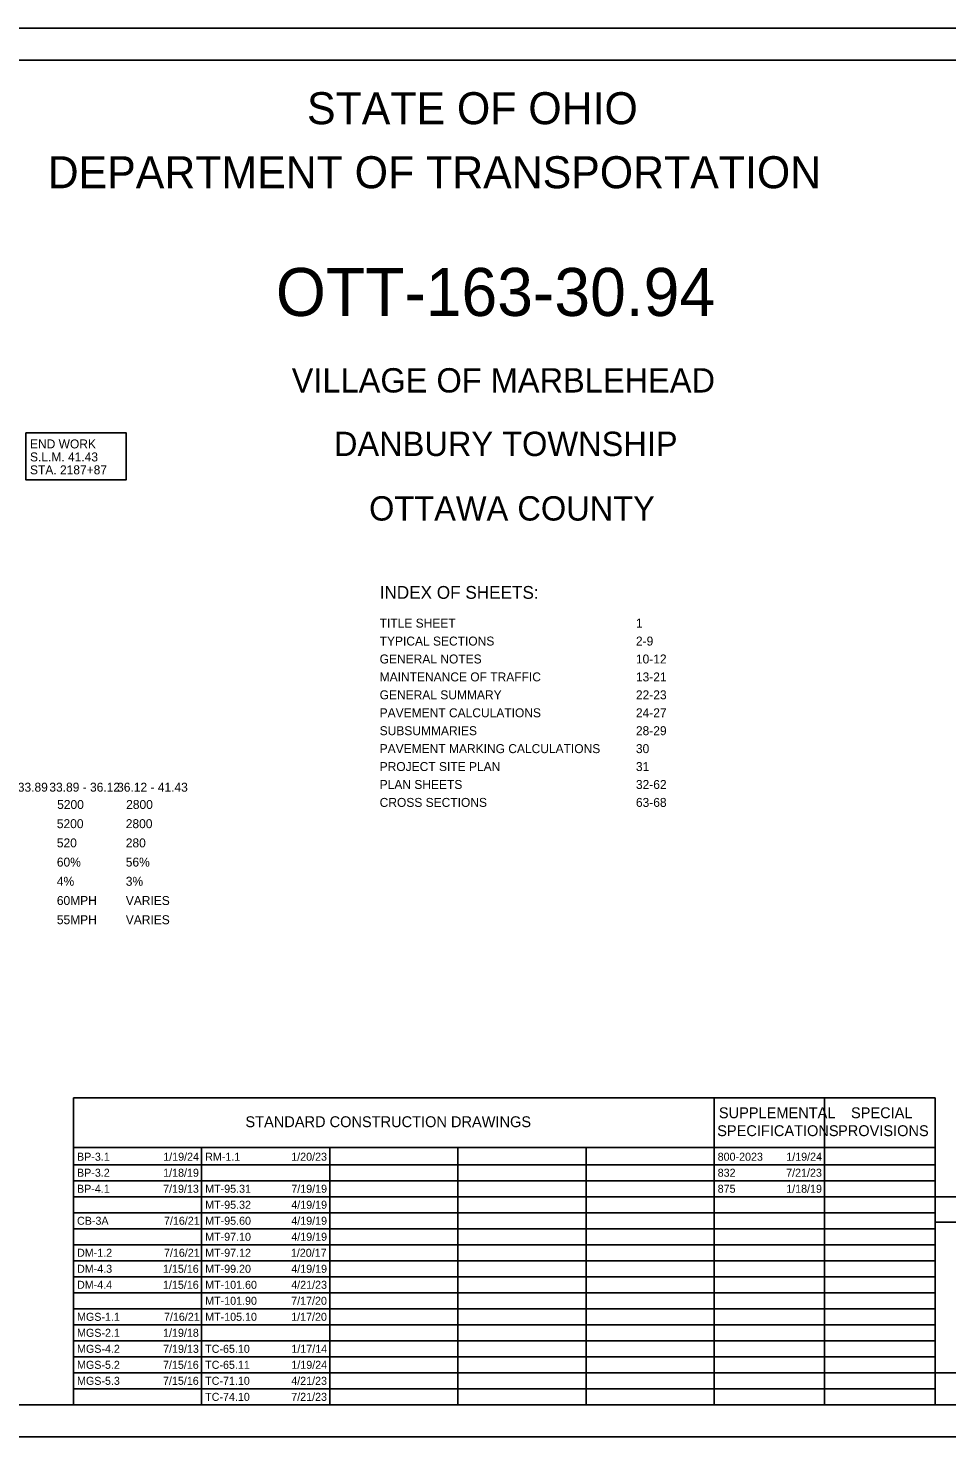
# Model space of a CAD drawing. Extents: x -12 to 34, y 0 to 22.
# Drawn here: x 9.44 to 23.78, y 0 to 22 of the extents above; entities that cross this region are included whole.
import ezdxf

# ---------------------------------------------------------------- set-up
doc = ezdxf.new("R2010")
doc.units = 0
for name, color, linetype in [('GM_X_Adjacent_County', 7, 'Continuous'), ('GM_X_County', 7, 'Continuous'), ('GM_X_Section', 7, 'Continuous'), ('GM_X_Township', 7, 'Continuous')]:
    doc.layers.add(name, color=color, linetype=linetype)

msp = doc.modelspace()

# ---------------------------------------------------------------- linework, layer by layer
at = {"layer": 'GM_X_Adjacent_County'}
msp.add_lwpolyline([(9.406, 15.682), (10.972, 15.682), (10.972, 14.944), (9.406, 14.944)], close=True, dxfattribs=at)
at = {"layer": 'GM_X_County'}
msp.add_lwpolyline([(1.5, 21.5), (33.5, 21.5), (33.5, 0.5), (1.5, 0.5)], close=True, dxfattribs=at)
at = {"layer": 'GM_X_Section'}
msp.add_lwpolyline([(0, 0), (34, 0), (34, 22), (0, 22)], close=True, dxfattribs=at)
at = {"layer": 'GM_X_Township'}
for p, q in [((10.15, 5.292), (23.6, 5.292)), ((10.15, 0.5), (10.15, 5.292)), ((20.15, 0.5), (20.15, 5.292)), ((21.875, 0.5), (21.875, 5.292)), ((23.6, 0.5), (23.6, 5.292)), ((10.15, 4.521), (23.6, 4.521)), ((12.15, 0.5), (12.15, 4.521)), ((14.15, 0.5), (14.15, 4.521)), ((16.15, 0.5), (16.15, 4.521)), ((18.15, 0.5), (18.15, 4.521)), ((10.15, 4.25), (23.6, 4.25)), ((10.15, 4), (23.6, 4)), ((10.15, 3.75), (23.6, 3.75)), ((23.6, 0.5), (23.6, 3.75)), ((23.6, 3.75), (26.4, 3.75)), ((10.15, 3.5), (23.6, 3.5)), ((23.6, 3.35), (26.4, 3.35)), ((10.15, 3.25), (23.6, 3.25)), ((10.15, 3), (23.6, 3)), ((10.15, 2.75), (23.6, 2.75)), ((10.15, 2.5), (23.6, 2.5)), ((10.15, 2.25), (23.6, 2.25)), ((10.15, 2), (23.6, 2)), ((10.15, 1.75), (23.6, 1.75)), ((10.15, 1.5), (23.6, 1.5)), ((10.15, 1.25), (23.6, 1.25)), ((10.15, 1), (23.6, 1)), ((10.15, 0.75), (23.6, 0.75)), ((23.6, 0.5), (26.4, 0.5))]:
    msp.add_line(p, q, dxfattribs=at)
msp.add_lwpolyline([(23.6, 0.5), (23.6, 1), (26.4, 1), (26.4, 0.5)], close=True, dxfattribs=at)

# ---------------------------------------------------------------- texts
at = {"layer": 'GM_X_Adjacent_County'}
for s, height, p in [('STATE OF OHIO', 0.5, (13.795, 20.5)), ('DEPARTMENT OF TRANSPORTATION', 0.5, (9.747, 19.5)), ('OTT-163-30.94', 0.75, (13.309, 17.505)), ('VILLAGE OF MARBLEHEAD', 0.38, (13.556, 16.31)), ('  DANBURY TOWNSHIP  ', 0.38, (13.933, 15.318)), ('END WORK', 0.14, (9.471, 15.437)), ('S.L.M. 41.43', 0.14, (9.471, 15.234)), ('STA. 2187+87', 0.14, (9.471, 15.032)), ('    OTTAWA COUNTY   ', 0.38, (14.199, 14.31)), ('INDEX OF SHEETS:', 0.2, (14.929, 13.088)), ('TITLE SHEET                        ', 0.14, (14.929, 12.638)), ('1      ', 0.14, (18.929, 12.638)), ('TYPICAL SECTIONS                   ', 0.14, (14.929, 12.358)), ('2-9    ', 0.14, (18.929, 12.358)), ('GENERAL NOTES                      ', 0.14, (14.929, 12.078)), ('10-12  ', 0.14, (18.929, 12.078)), ('MAINTENANCE OF TRAFFIC             ', 0.14, (14.929, 11.798)), ('13-21  ', 0.14, (18.929, 11.798)), ('GENERAL SUMMARY                    ', 0.14, (14.929, 11.518)), ('22-23  ', 0.14, (18.929, 11.518)), ('PAVEMENT CALCULATIONS              ', 0.14, (14.929, 11.238)), ('24-27  ', 0.14, (18.929, 11.238)), ('SUBSUMMARIES                       ', 0.14, (14.929, 10.958)), ('28-29  ', 0.14, (18.929, 10.958)), ('PAVEMENT MARKING CALCULATIONS      ', 0.14, (14.929, 10.678)), ('30     ', 0.14, (18.929, 10.678)), ('PROJECT SITE PLAN                  ', 0.14, (14.929, 10.398)), ('31     ', 0.14, (18.929, 10.398)), ('PLAN SHEETS                        ', 0.14, (14.929, 10.118)), ('32-62  ', 0.14, (18.929, 10.118)), ('5200  ', 0.14, (9.895, 9.806)), ('2800  ', 0.14, (10.972, 9.806)), ('CROSS SECTIONS                     ', 0.14, (14.929, 9.838)), ('63-68  ', 0.14, (18.929, 9.838)), ('5200  ', 0.14, (9.89, 9.506)), ('2800  ', 0.14, (10.966, 9.506)), ('520   ', 0.14, (9.89, 9.206)), ('280   ', 0.14, (10.966, 9.206)), ('60%   ', 0.14, (9.89, 8.906)), ('56%   ', 0.14, (10.966, 8.906)), ('4%    ', 0.14, (9.89, 8.606)), ('3%    ', 0.14, (10.966, 8.606)), ('60MPH ', 0.14, (9.89, 8.306)), ('VARIES', 0.14, (10.966, 8.306)), ('55MPH ', 0.14, (9.89, 8.006)), ('VARIES', 0.14, (10.966, 8.006)), ('SUPPLEMENTAL', 0.17, (20.224, 4.976)), ('SPECIAL', 0.17, (22.286, 4.976)), ('STANDARD CONSTRUCTION DRAWINGS', 0.17, (12.834, 4.836)), ('SPECIFICATIONS', 0.17, (20.198, 4.696)), ('PROVISIONS', 0.17, (22.084, 4.696))]:
    msp.add_text(s, height=height, dxfattribs=at).set_placement(p)
at = {"layer": 'GM_X_Township'}
for s, height, p in [('31.77 - 33.89', 0.14, (8.646, 10.076)), ('33.89 - 36.12', 0.14, (9.773, 10.076)), ('36.12 - 41.43', 0.14, (10.831, 10.076)), ('BP-3.1', 0.125, (10.205, 4.312)), ('1/19/24', 0.125, (11.551, 4.312)), ('RM-1.1', 0.125, (12.205, 4.312)), ('1/20/23', 0.125, (13.549, 4.312)), ('800-2023', 0.125, (20.205, 4.312)), ('1/19/24', 0.125, (21.276, 4.312)), ('BP-3.2', 0.125, (10.205, 4.062)), ('1/18/19', 0.125, (11.55, 4.062)), ('832', 0.125, (20.205, 4.062)), ('7/21/23', 0.125, (21.274, 4.062)), ('-', 0.125, (21.768, 4.312)), ('BP-4.1', 0.125, (10.205, 3.812)), ('7/19/13', 0.125, (11.549, 3.812)), ('MT-95.31', 0.125, (12.205, 3.812)), ('7/19/19', 0.125, (13.55, 3.812)), ('875', 0.125, (20.205, 3.812)), ('1/18/19', 0.125, (21.275, 3.812)), ('MT-95.32', 0.125, (12.205, 3.562)), ('4/19/19', 0.125, (13.55, 3.562)), ('CB-3A', 0.125, (10.205, 3.312)), ('7/16/21', 0.125, (11.562, 3.312)), ('MT-95.60', 0.125, (12.205, 3.312)), ('4/19/19', 0.125, (13.55, 3.312)), ('MT-97.10', 0.125, (12.205, 3.062)), ('4/19/19', 0.125, (13.55, 3.062)), ('DM-1.2', 0.125, (10.205, 2.812)), ('7/16/21', 0.125, (11.562, 2.812)), ('MT-97.12', 0.125, (12.205, 2.812)), ('1/20/17', 0.125, (13.543, 2.812)), ('DM-4.3', 0.125, (10.205, 2.562)), ('1/15/16', 0.125, (11.547, 2.562)), ('MT-99.20', 0.125, (12.205, 2.562)), ('4/19/19', 0.125, (13.55, 2.562)), ('DM-4.4', 0.125, (10.205, 2.312)), ('1/15/16', 0.125, (11.547, 2.312)), ('MT-101.60', 0.125, (12.205, 2.312)), ('4/21/23', 0.125, (13.549, 2.312)), ('MT-101.90', 0.125, (12.205, 2.062)), ('7/17/20', 0.125, (13.548, 2.062)), ('MGS-1.1', 0.125, (10.205, 1.812)), ('7/16/21', 0.125, (11.562, 1.812)), ('MT-105.10', 0.125, (12.205, 1.812)), ('1/17/20', 0.125, (13.548, 1.812)), ('MGS-2.1', 0.125, (10.205, 1.562)), ('1/19/18', 0.125, (11.548, 1.562)), ('MGS-4.2', 0.125, (10.205, 1.312)), ('7/19/13', 0.125, (11.549, 1.312)), ('TC-65.10', 0.125, (12.205, 1.312)), ('1/17/14', 0.125, (13.551, 1.312)), ('MGS-5.2', 0.125, (10.205, 1.062)), ('7/15/16', 0.125, (11.547, 1.062)), ('TC-65.11', 0.125, (12.205, 1.062)), ('1/19/24', 0.125, (13.551, 1.062)), ('MGS-5.3', 0.125, (10.205, 0.812)), ('7/15/16', 0.125, (11.547, 0.812)), ('TC-71.10', 0.125, (12.205, 0.812)), ('4/21/23', 0.125, (13.549, 0.812)), ('TC-74.10', 0.125, (12.205, 0.562)), ('7/21/23', 0.125, (13.549, 0.562))]:
    msp.add_text(s, height=height, dxfattribs=at).set_placement(p)

doc.saveas('drawing.dxf')
